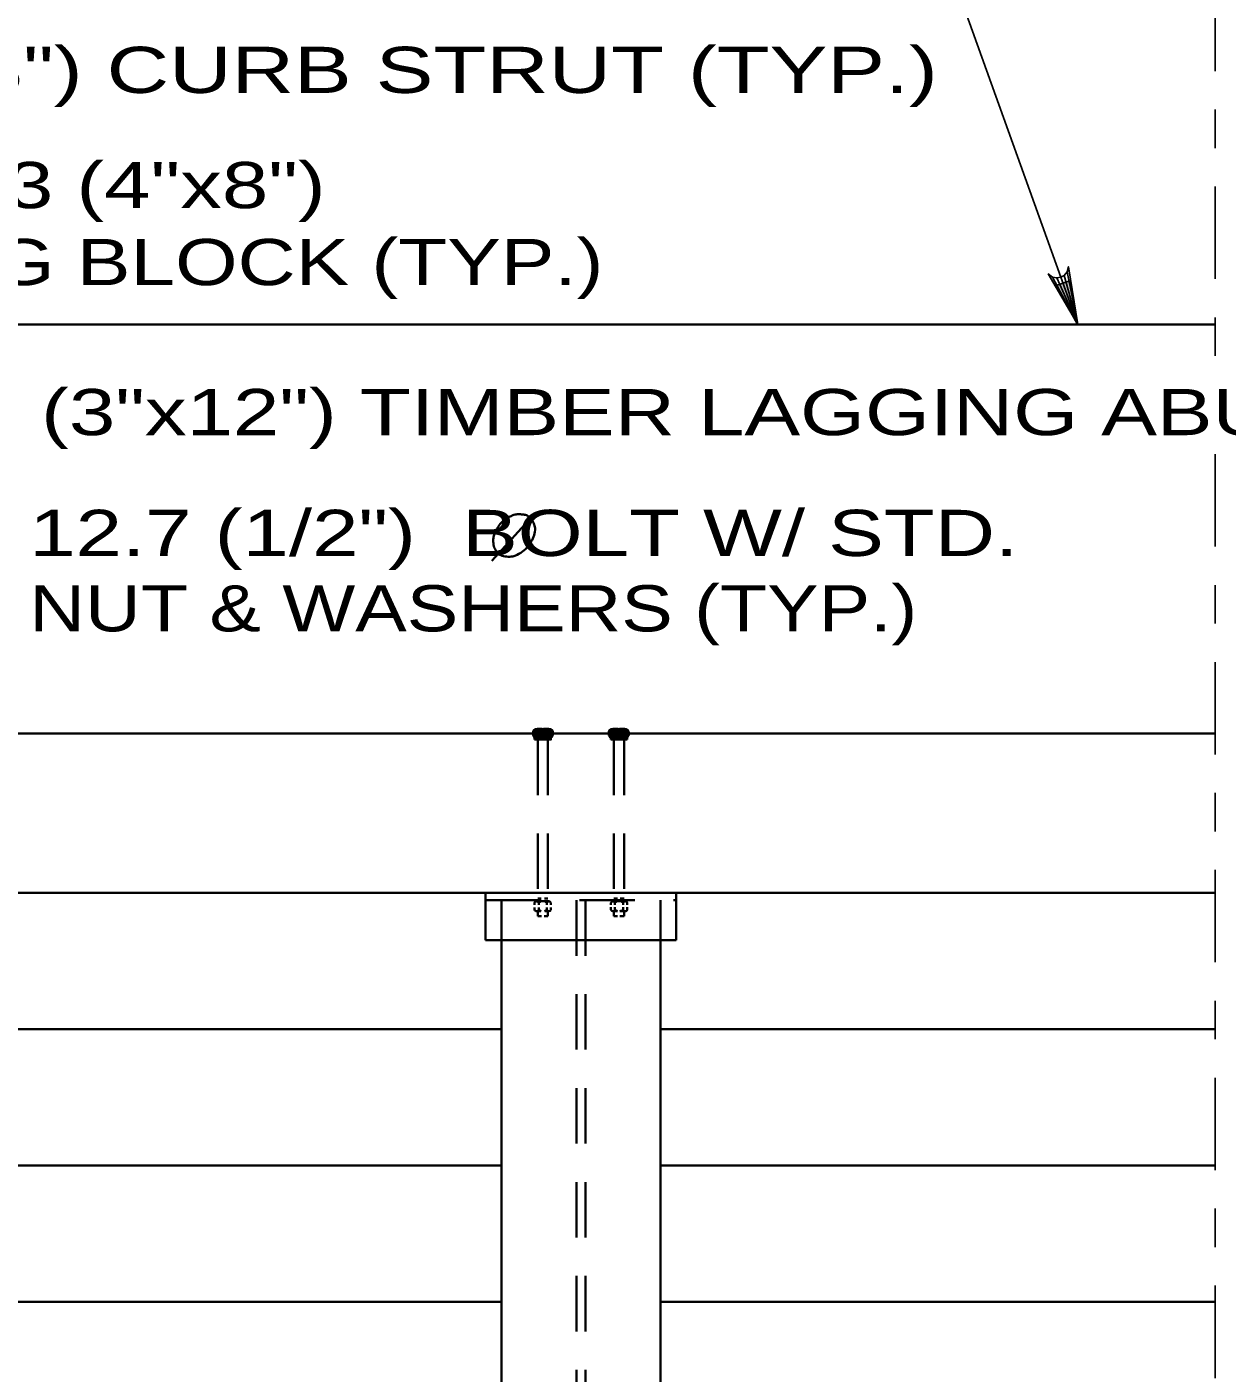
# Model space of a CAD drawing. Extents: x -6.4 to 73.1, y -66 to 0.
# Drawn here: x 44.879 to 47.996, y -39.753 to -36.256 of the extents above; entities that cross this region are included whole.
import ezdxf

# ---------------------------------------------------------------- set-up
doc = ezdxf.new("R2010")
doc.units = 0
doc.header["$LTSCALE"] = 0.048
doc.header["$PDMODE"] = 32
doc.header["$PDSIZE"] = 0.024
doc.linetypes.add('DOT_DASHED', pattern=[7.7, 5, -1.2, 0.3, -1.2])
doc.linetypes.add('MEDIUM_DASHED', pattern=[4.5, 3, -1.5])
for name, color, linetype, lineweight in [('3', 7, 'Continuous', 35), ('4', 7, 'Continuous', 25), ('5', 7, 'Continuous', 25), ('8', 7, 'Continuous', 25)]:
    doc.layers.add(name, color=color, linetype=linetype, lineweight=lineweight)

msp = doc.modelspace()

# ---------------------------------------------------------------- hatches: boundary and pattern name
at = {"layer": '4'}
msp.add_hatch(color=256, dxfattribs=at).paths.add_polyline_path([(47.58775, -36.91525), (47.55208, -36.92775), (47.6075, -37.0285)])

# ---------------------------------------------------------------- linework, layer by layer
at = {"layer": '3'}
for p, q in [((42.54183, -37.0285), (47.96558, -37.0285)), ((41.69675, -38.09142), (47.96558, -38.09142)), ((46.1975, -38.10725), (46.1975, -38.09508)), ((46.23517, -38.09133), (46.20283, -38.09133)), ((46.2085, -38.09508), (46.2085, -38.10725)), ((46.22983, -38.09508), (46.22983, -38.10725)), ((46.39533, -38.10725), (46.39533, -38.09508)), ((46.43792, -38.10725), (46.39533, -38.10725)), ((46.40025, -38.09133), (46.43258, -38.09133)), ((46.40558, -38.09508), (46.40558, -38.10725)), ((46.42692, -38.09508), (46.42692, -38.10725)), ((46.43792, -38.10725), (46.43792, -38.09508)), ((41.69675, -38.50483), (47.96558, -38.50483)), ((46.07017, -38.50483), (46.07017, -38.62783)), ((46.19708, -38.53625), (46.19708, -38.53092)), ((46.23483, -38.52717), (46.20242, -38.52717)), ((46.21458, -38.51992), (46.20567, -38.51992)), ((46.20817, -38.53092), (46.20817, -38.53625)), ((46.23192, -38.51992), (46.22358, -38.51992)), ((46.2295, -38.53092), (46.2295, -38.53625)), ((46.23975, -38.53625), (46.23975, -38.53092)), ((46.39567, -38.53683), (46.39567, -38.53092)), ((46.40067, -38.52717), (46.433, -38.52717)), ((46.4035, -38.51992), (46.413, -38.51992)), ((46.406, -38.53092), (46.406, -38.53683)), ((46.42017, -38.51992), (46.42975, -38.51992)), ((46.42733, -38.53092), (46.42733, -38.53683)), ((46.43833, -38.53683), (46.43833, -38.53092)), ((46.56533, -38.50483), (46.56533, -38.62783)), ((46.19708, -38.54925), (46.19708, -38.543)), ((46.2135, -38.553), (46.20242, -38.553)), ((46.20567, -38.553), (46.20567, -38.56583)), ((46.21517, -38.56583), (46.20567, -38.56583)), ((46.20817, -38.543), (46.20817, -38.54925)), ((46.23192, -38.56583), (46.22242, -38.56583)), ((46.23483, -38.553), (46.224, -38.553)), ((46.2295, -38.543), (46.2295, -38.54925)), ((46.23192, -38.553), (46.23192, -38.56583)), ((46.23975, -38.54925), (46.23975, -38.543)), ((46.39567, -38.54925), (46.39567, -38.54292)), ((46.40067, -38.553), (46.413, -38.553)), ((46.4035, -38.553), (46.4035, -38.56583)), ((46.4035, -38.56583), (46.413, -38.56583)), ((46.406, -38.54292), (46.406, -38.54925)), ((46.419, -38.553), (46.433, -38.553)), ((46.419, -38.56583), (46.42975, -38.56583)), ((46.42733, -38.54292), (46.42733, -38.54925)), ((46.42975, -38.553), (46.42975, -38.56583)), ((46.43833, -38.54925), (46.43833, -38.54292)), ((46.07017, -38.62783), (46.56533, -38.62783)), ((46.11108, -38.62783), (46.11108, -40.37758)), ((46.52433, -38.62783), (46.52433, -40.37758)), ((44.39833, -38.85917), (46.11108, -38.85917)), ((46.52433, -38.85917), (47.96558, -38.85917)), ((44.39833, -39.2135), (46.11108, -39.2135)), ((46.52433, -39.2135), (47.96558, -39.2135)), ((44.39833, -39.56783), (46.11108, -39.56783)), ((46.52433, -39.56783), (47.96558, -39.56783))]:
    msp.add_line(p, q, dxfattribs=at)
at = {"layer": '3', "linetype": 'MEDIUM_DASHED'}
for p, q in [((46.20567, -38.10725), (46.20567, -38.52717)), ((46.23192, -38.10725), (46.23192, -38.52717)), ((46.4035, -38.10725), (46.4035, -38.52717)), ((46.42975, -38.10725), (46.42975, -38.52717))]:
    msp.add_line(p, q, dxfattribs=at)
at = {"layer": '3'}
msp.add_lwpolyline([(46.1975, -38.10725), (46.24008, -38.10725), (46.24008, -38.09508)], dxfattribs=at)
for centre, radius, start, end in [((46.20298, -38.09721), 0.00592, 88.17294, 158.71305), ((46.20298, -38.09721), 0.00592, 21.28694, 88.17294), ((46.21916, -38.10825), 0.01696, 51.05, 128.95), ((46.23497, -38.09668), 0.00539, 17.45181, 162.54819), ((46.40044, -38.09668), 0.00539, 17.45181, 162.54819), ((46.41625, -38.10825), 0.01696, 51.05, 128.95), ((46.43243, -38.09721), 0.00592, 91.82706, 158.71306), ((46.43243, -38.09721), 0.00592, 21.28694, 91.82706), ((46.20265, -38.5331), 0.00592, 88.17294, 158.71305), ((46.20265, -38.5331), 0.00592, 21.28694, 88.17294), ((46.21883, -38.54413), 0.01696, 51.05, 128.95), ((46.23464, -38.53256), 0.00539, 17.45181, 162.54819), ((46.40087, -38.53256), 0.00539, 17.45181, 162.54819), ((46.41667, -38.54413), 0.01696, 51.05, 128.95), ((46.43285, -38.5331), 0.00592, 91.82706, 158.71306), ((46.43285, -38.5331), 0.00592, 21.28694, 91.82706), ((46.20265, -38.54708), 0.00592, 201.28694, 271.82706), ((46.20265, -38.54708), 0.00592, 271.82706, 338.71306), ((46.21883, -38.53604), 0.01696, 231.05, 256.0077), ((46.21883, -38.53604), 0.01696, 284.34274, 308.95), ((46.23464, -38.54761), 0.00539, 197.45181, 342.54819), ((46.40087, -38.54761), 0.00539, 197.45181, 342.54819), ((46.41667, -38.53604), 0.01696, 231.05, 257.49177), ((46.41667, -38.53604), 0.01696, 277.88621, 308.95), ((46.43285, -38.54708), 0.00592, 201.28694, 268.17294), ((46.43285, -38.54708), 0.00592, 268.17294, 338.71305)]:
    msp.add_arc(centre, radius, start, end, dxfattribs=at)
for p in [(46.20467, -38.0915), (46.20525, -38.0915), (46.20583, -38.0915), (46.20608, -38.09208), (46.20642, -38.0915), (46.20675, -38.09208), (46.207, -38.0915), (46.207, -38.09267), (46.20733, -38.09208), (46.20758, -38.0915), (46.20758, -38.09267), (46.20792, -38.09208), (46.20792, -38.09325), (46.20817, -38.0915), (46.20817, -38.09267), (46.20817, -38.09383), (46.2085, -38.09208), (46.2085, -38.09325), (46.2085, -38.09442), (46.20883, -38.0915), (46.20883, -38.09267), (46.20883, -38.09383), (46.20908, -38.09208), (46.20908, -38.09325), (46.20908, -38.09442), (46.20933, -38.0915), (46.20933, -38.09267), (46.20933, -38.09383), (46.20967, -38.09208), (46.20967, -38.09325), (46.20992, -38.0915), (46.20992, -38.09267), (46.20992, -38.09383), (46.21025, -38.09208), (46.21025, -38.09325), (46.21058, -38.0915), (46.21058, -38.09267), (46.21083, -38.09208), (46.21083, -38.09325), (46.21117, -38.0915), (46.21117, -38.09267), (46.21142, -38.09208), (46.21175, -38.0915), (46.21175, -38.09267), (46.212, -38.09208), (46.21233, -38.0915), (46.21233, -38.09267), (46.21258, -38.09208), (46.21292, -38.0915), (46.21317, -38.09208), (46.2135, -38.0915), (46.21383, -38.09208), (46.21408, -38.0915), (46.21467, -38.0915), (46.21525, -38.0915), (46.21592, -38.0915), (46.21642, -38.0915), (46.22175, -38.0915), (46.22233, -38.0915), (46.223, -38.0915), (46.2235, -38.0915), (46.22417, -38.0915), (46.22442, -38.09208), (46.22475, -38.0915), (46.225, -38.09208), (46.22533, -38.0915), (46.22558, -38.09208), (46.22592, -38.0915), (46.22592, -38.09267), (46.22625, -38.09208), (46.2265, -38.0915), (46.2265, -38.09267), (46.22675, -38.09208), (46.22708, -38.0915), (46.22708, -38.09267), (46.22733, -38.09208), (46.22733, -38.09325), (46.22767, -38.0915), (46.22767, -38.09267), (46.228, -38.09208), (46.228, -38.09325), (46.22825, -38.0915), (46.22825, -38.09267), (46.22825, -38.09383), (46.22858, -38.09208), (46.22858, -38.09325), (46.22883, -38.0915), (46.22883, -38.09267), (46.22883, -38.09383), (46.22917, -38.09208), (46.22917, -38.09325), (46.22917, -38.09442), (46.22942, -38.0915), (46.22942, -38.09267), (46.22942, -38.09383), (46.22975, -38.09208), (46.22975, -38.09325), (46.22975, -38.09442), (46.22983, -38.09208), (46.22983, -38.09325), (46.22983, -38.09442), (46.23017, -38.0915), (46.23017, -38.09267), (46.23017, -38.09383), (46.23042, -38.09208), (46.23042, -38.09325), (46.23075, -38.0915), (46.23075, -38.09267), (46.231, -38.09208), (46.23133, -38.0915), (46.23133, -38.09267), (46.23158, -38.09208), (46.23192, -38.0915), (46.23225, -38.09208), (46.2325, -38.0915), (46.23308, -38.0915), (46.23367, -38.0915), (46.40175, -38.0915), (46.40233, -38.0915), (46.40292, -38.0915), (46.40317, -38.09208), (46.4035, -38.0915), (46.40383, -38.09208), (46.40408, -38.0915), (46.40408, -38.09267), (46.40442, -38.09208), (46.40467, -38.0915), (46.40467, -38.09267), (46.405, -38.09208), (46.405, -38.09325), (46.40525, -38.0915), (46.40525, -38.09267), (46.40525, -38.09383), (46.40558, -38.09208), (46.40558, -38.09325), (46.40558, -38.09442), (46.40567, -38.09208), (46.40567, -38.09325), (46.40567, -38.09442), (46.40592, -38.0915), (46.40592, -38.09267), (46.40592, -38.09383), (46.40625, -38.09208), (46.40625, -38.09325), (46.40625, -38.09442), (46.40658, -38.0915), (46.40658, -38.09267), (46.40658, -38.09383), (46.40683, -38.09208), (46.40683, -38.09325), (46.40717, -38.0915), (46.40717, -38.09267), (46.40717, -38.09383), (46.40742, -38.09208), (46.40742, -38.09325), (46.40775, -38.0915), (46.40775, -38.09267), (46.408, -38.09208), (46.408, -38.09325), (46.40833, -38.0915), (46.40833, -38.09267), (46.40867, -38.09208), (46.40892, -38.0915), (46.40892, -38.09267), (46.40917, -38.09208), (46.4095, -38.0915), (46.4095, -38.09267), (46.40983, -38.09208), (46.41008, -38.0915), (46.41042, -38.09208), (46.41067, -38.0915), (46.411, -38.09208), (46.41125, -38.0915), (46.41192, -38.0915), (46.41242, -38.0915), (46.41308, -38.0915), (46.41367, -38.0915), (46.419, -38.0915), (46.4195, -38.0915), (46.42017, -38.0915), (46.42075, -38.0915), (46.42133, -38.0915), (46.42158, -38.09208), (46.42192, -38.0915), (46.42225, -38.09208), (46.4225, -38.0915), (46.42283, -38.09208), (46.42308, -38.0915), (46.42308, -38.09267), (46.42333, -38.09208), (46.42367, -38.0915), (46.42367, -38.09267), (46.424, -38.09208), (46.42425, -38.0915), (46.42425, -38.09267), (46.42458, -38.09208), (46.42458, -38.09325), (46.42483, -38.0915), (46.42483, -38.09267), (46.42517, -38.09208), (46.42517, -38.09325), (46.42542, -38.0915), (46.42542, -38.09267), (46.42542, -38.09383), (46.42575, -38.09208), (46.42575, -38.09325), (46.42608, -38.0915), (46.42608, -38.09267), (46.42608, -38.09383), (46.42633, -38.09208), (46.42633, -38.09325), (46.42633, -38.09442), (46.42658, -38.0915), (46.42658, -38.09267), (46.42658, -38.09383), (46.42692, -38.09208), (46.42692, -38.09325), (46.42692, -38.09442), (46.42725, -38.0915), (46.42725, -38.09267), (46.42725, -38.09383), (46.4275, -38.09208), (46.4275, -38.09325), (46.42783, -38.0915), (46.42783, -38.09267), (46.42808, -38.09208), (46.42842, -38.0915), (46.42842, -38.09267), (46.42867, -38.09208), (46.429, -38.0915), (46.42933, -38.09208), (46.42958, -38.0915), (46.43017, -38.0915), (46.43075, -38.0915)]:
    msp.add_point(p, dxfattribs=at)
at = {"layer": '4'}
msp.add_line((47.60825, -37.0285), (47.25583, -36.045), dxfattribs=at)
at = {"layer": '4', "linetype": 'DOT_DASHED'}
for p, q in [((47.96558, -36.13033), (47.96558, -37.16192)), ((47.96558, -37.36575), (47.96558, -41.76792))]:
    msp.add_line(p, q, dxfattribs=at)
at = {"layer": '4'}
msp.add_lwpolyline([(47.60825, -37.0285), (47.53158, -36.89758), (47.543, -36.90567), (47.55442, -36.90792), (47.56442, -36.90608), (47.57325, -36.90117), (47.58067, -36.89217), (47.58425, -36.87867), (47.60825, -37.0285), (47.58067, -36.89217), (47.57325, -36.90117), (47.60825, -37.0285), (47.56442, -36.90608), (47.55442, -36.90792), (47.60825, -37.0285), (47.543, -36.90567)], dxfattribs=at)
msp.add_lwpolyline([(47.58775, -36.91525), (47.55208, -36.92775), (47.6075, -37.0285)], close=True, dxfattribs=at)
at = {"layer": '5', "lineweight": 35}
msp.add_line((46.0865, -37.6425), (46.1985, -37.51992), dxfattribs=at)
msp.add_spline([(46.18683, -37.532), (46.17808, -37.52517), (46.16933, -37.52275), (46.15833, -37.52175), (46.15208, -37.52175), (46.14133, -37.52425), (46.1315, -37.52875), (46.12458, -37.53267), (46.11133, -37.54325), (46.101, -37.55675), (46.09475, -37.56942), (46.09108, -37.581), (46.09, -37.59175), (46.09108, -37.601), (46.09558, -37.61417), (46.10033, -37.621), (46.11, -37.62825), (46.1245, -37.63175), (46.141, -37.63125), (46.16183, -37.62175), (46.17708, -37.60867), (46.18858, -37.59275), (46.19608, -37.57617), (46.19858, -37.55775), (46.19533, -37.54592), (46.18733, -37.532)], degree=3, dxfattribs=at)
at = {"layer": '8', "linetype": 'MEDIUM_DASHED', "lineweight": 35}
for p, q in [((46.07017, -38.5245), (46.56533, -38.5245)), ((46.11117, -38.5245), (46.11117, -38.62783)), ((46.306, -38.5245), (46.306, -42.159)), ((46.32958, -38.5245), (46.32958, -42.17383)), ((46.52433, -38.5245), (46.52433, -38.62783))]:
    msp.add_line(p, q, dxfattribs=at)

# ---------------------------------------------------------------- texts
at = {"layer": '4'}
for s, width, p in [('12.7 (1/2")  BOLT W/ STD.', 1.35, (44.88475, -37.63025)), ('NUT & WASHERS (TYP.)', 1.25, (44.88475, -37.82608))]:
    msp.add_text(s, height=0.12, dxfattribs=dict(at, width=width)).set_placement(p)
at = {"layer": '5'}
for s, width, p in [('102x203 (4"x8") CURB STRUT (TYP.)', 1.4, (43.42767, -36.42733)), ('102x203 (4"x8")', 1.35, (44.11592, -36.72658)), ('NAILING BLOCK (TYP.)', 1.3, (44.11592, -36.92658)), ('76x305 (3"x12") TIMBER LAGGING ABUT.', 1.35, (44.14467, -37.31633))]:
    msp.add_text(s, height=0.12, dxfattribs=dict(at, width=width)).set_placement(p)

doc.saveas('drawing.dxf')
